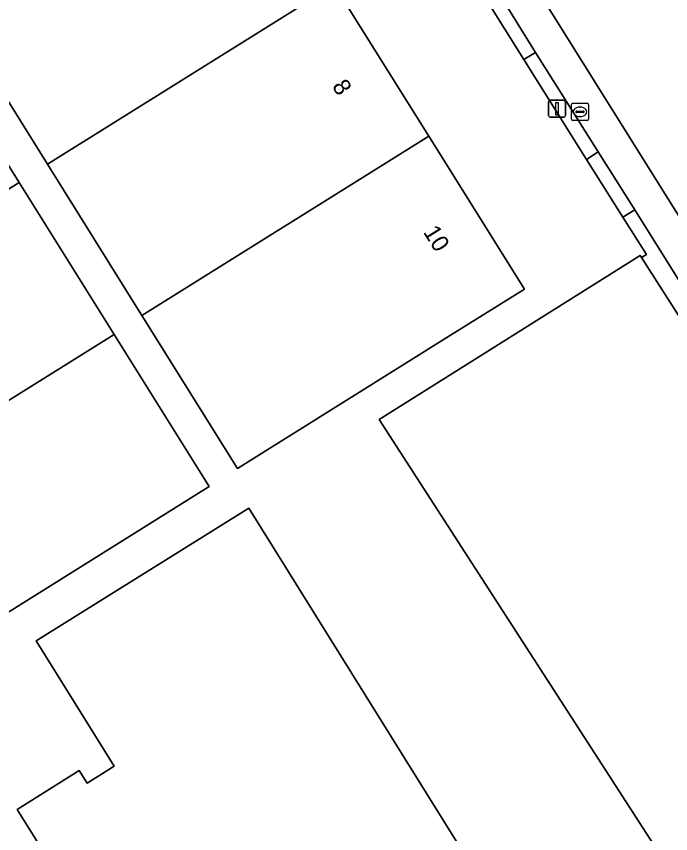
# Model space of a CAD drawing. Extents: x 158455 to 159797, y 387218 to 388672.
# Drawn here: x 158762.56 to 158800.91, y 387815.4 to 387863.3 of the extents above; entities that cross this region are included whole.
import ezdxf

# ---------------------------------------------------------------- set-up
doc = ezdxf.new("R2010")
doc.units = 0
for name, color, linetype in [('IMGEO_Brandkraan', 7, 'Continuous'), ('IMGEO_Erf', 7, 'Continuous'), ('IMGEO_Lichtmast', 7, 'Continuous'), ('IMGEO_Pand', 7, 'Continuous'), ('IMGEO_Pand_nummerreeks', 7, 'Continuous'), ('IMGEO_Parkeervlak_open', 7, 'Continuous'), ('IMGEO_Rijbaan_lokaal_gesloten', 7, 'Continuous'), ('IMGEO_Voetpad_open', 7, 'Continuous')]:
    doc.layers.add(name, color=color, linetype=linetype)

msp = doc.modelspace()

# ---------------------------------------------------------------- linework, layer by layer
at = {"layer": 'IMGEO_Brandkraan'}
for p, q in [((158795.095, 387857.277), (158795.095, 387858.129)), ((158795.17, 387858.203), (158796.022, 387858.203)), ((158795.583, 387857.983), (158795.608, 387857.983)), ((158796.096, 387858.129), (158796.096, 387857.277)), ((158795.354, 387857.697), (158795.354, 387857.709)), ((158795.792, 387857.66), (158795.394, 387857.66)), ((158795.397, 387857.746), (158795.795, 387857.746)), ((158795.606, 387857.423), (158795.581, 387857.423)), ((158795.838, 387857.709), (158795.838, 387857.697)), ((158796.022, 387857.203), (158795.17, 387857.203))]:
    msp.add_line(p, q, dxfattribs=at)
for points in [[(158795.095, 387857.277), (158795.095, 387858.129)], [(158795.17, 387858.203), (158796.022, 387858.203)], [(158796.096, 387858.129), (158796.096, 387857.277)], [(158796.022, 387857.203), (158795.17, 387857.203)]]:
    msp.add_lwpolyline(points, dxfattribs=at)
for centre, radius, start, end in [((158795.172, 387858.127), 0.0765, 91.552, 178.448), ((158795.172, 387858.127), 0.0765, 91.552, 178.448), ((158796.02, 387858.127), 0.0765, 1.552, 88.448), ((158796.02, 387858.127), 0.0765, 1.552, 88.448), ((158795.394, 387857.706), 0.0403, 85.8775, 175.7526), ((158795.391, 387857.696), 0.0366, 178.938, 274.7102), ((158795.795, 387857.703), 0.043, 264.8664, 352.4533), ((158795.799, 387857.708), 0.0386, 1.7309, 96.639), ((158795.172, 387857.279), 0.0765, 181.552, 268.448), ((158795.172, 387857.279), 0.0765, 181.552, 268.448), ((158796.02, 387857.279), 0.0765, 271.552, 358.448), ((158796.02, 387857.279), 0.0765, 271.552, 358.448)]:
    msp.add_arc(centre, radius, start, end, dxfattribs=at)
for centre, major_axis, ratio, start_param, end_param in [((158795.582, 387857.703), (-0.387, 0.002), 0.722429, 4.712389, 7.853982), ((158795.607, 387857.703), (-0.39, 0.002), 0.717154, 1.570796, 4.712389)]:
    msp.add_ellipse(centre, major_axis=major_axis, ratio=ratio, start_param=start_param, end_param=end_param, dxfattribs=at)
at = {"layer": 'IMGEO_Erf'}
for points in [[(158800.488, 387813.876), (158783.815, 387839.674), (158799.126, 387849.283), (158799.192, 387849.165), (158799.495, 387849.349), (158798.107, 387851.535), (158795.971, 387854.919), (158792.311, 387860.769), (158790.068, 387864.352), (158787.01, 387869.188), (158784.775, 387872.783), (158776.797, 387885.577), (158774.665, 387888.991), (158773.366, 387891.042)], [(158771.452, 387802.636), (158762.604, 387816.822), (158766.252, 387819.098), (158766.712, 387818.361), (158768.299, 387819.351), (158763.717, 387826.697), (158776.177, 387834.469), (158789.093, 387813.763)]]:
    msp.add_lwpolyline(points, dxfattribs=at)
for points in [[(158775.523, 387836.811), (158769.92, 387845.776), (158764.379, 387854.641), (158758.776, 387863.607), (158771.346, 387871.463), (158775.586, 387874.113), (158781.189, 387865.148), (158786.73, 387856.283), (158792.333, 387847.317), (158788.093, 387844.667)], [(158761.356, 387827.942), (158757.115, 387825.292), (158751.55, 387834.196), (158745.985, 387843.102), (158740.419, 387852.007), (158744.66, 387854.657), (158757.16, 387862.47), (158762.726, 387853.564), (158768.292, 387844.658), (158773.856, 387835.755)]]:
    msp.add_lwpolyline(points, close=True, dxfattribs=at)
at = {"layer": 'IMGEO_Lichtmast'}
for p, q in [((158793.849, 387858.384), (158794.639, 387858.384)), ((158794.639, 387858.384), (158793.849, 387858.384)), ((158793.749, 387857.484), (158793.749, 387858.284)), ((158793.749, 387858.284), (158793.749, 387857.484)), ((158794.739, 387858.284), (158794.739, 387857.484)), ((158794.739, 387857.484), (158794.739, 387858.284)), ((158794.639, 387857.384), (158793.849, 387857.384)), ((158793.849, 387857.384), (158794.639, 387857.384))]:
    msp.add_line(p, q, dxfattribs=at)
msp.add_lwpolyline([(158794.169, 387858.259), (158794.319, 387858.259), (158794.319, 387857.509), (158794.169, 387857.509), (158794.169, 387858.259)], dxfattribs=at)
for centre, start, end in [((158793.849, 387858.284), 90, 180), ((158793.849, 387858.284), 90, 180), ((158794.639, 387858.284), 0, 90), ((158794.639, 387858.284), 360, 90), ((158793.849, 387857.484), 180, 270), ((158793.849, 387857.484), 180, 270), ((158794.639, 387857.484), 270, 0), ((158794.639, 387857.484), 270, 0)]:
    msp.add_arc(centre, 0.1, start, end, dxfattribs=at)
at = {"layer": 'IMGEO_Pand'}
for points in [[(158764.379, 387854.641), (158781.189, 387865.148), (158775.586, 387874.113), (158771.346, 387871.463), (158758.776, 387863.607)], [(158769.92, 387845.776), (158786.73, 387856.283), (158781.189, 387865.148), (158764.379, 387854.641)], [(158762.726, 387853.564), (158757.16, 387862.47), (158744.66, 387854.657), (158740.419, 387852.007), (158745.985, 387843.102)], [(158769.92, 387845.776), (158775.523, 387836.811), (158788.093, 387844.667), (158792.333, 387847.317), (158786.73, 387856.283)], [(158768.292, 387844.658), (158762.726, 387853.564), (158745.985, 387843.102), (158751.55, 387834.196)], [(158800.488, 387813.876), (158813.131, 387821.784), (158814.073, 387825.912), (158799.192, 387849.165), (158799.126, 387849.283), (158783.815, 387839.674)], [(158768.292, 387844.658), (158751.55, 387834.196), (158757.115, 387825.292), (158761.356, 387827.942), (158773.856, 387835.755)], [(158779.847, 387800.742), (158789.812, 387806.958), (158787.506, 387810.654), (158786.782, 387810.203), (158785.831, 387811.728), (158789.093, 387813.763), (158776.177, 387834.469), (158763.717, 387826.697), (158768.299, 387819.351), (158766.712, 387818.361), (158766.252, 387819.098), (158762.604, 387816.822), (158771.452, 387802.636), (158774.397, 387804.473), (158775.793, 387802.235), (158778.041, 387803.637)]]:
    msp.add_lwpolyline(points, close=True, dxfattribs=at)
at = {"layer": 'IMGEO_Parkeervlak_open'}
for points in [[(158815.162, 387829.602), (158779.898, 387885.947)], [(158779.996, 387884.757), (158779.635, 387882.852), (158779.716, 387882.386), (158785.476, 387873.211), (158787.718, 387869.63), (158790.757, 387864.802), (158792.992, 387861.187), (158796.666, 387855.36), (158798.808, 387851.952), (158811.691, 387831.345), (158811.738, 387831.253), (158812.129, 387830.976), (158813.993, 387830.436)]]:
    msp.add_lwpolyline(points, dxfattribs=at)
at = {"layer": 'IMGEO_Rijbaan_lokaal_gesloten'}
msp.add_lwpolyline([(158809.048, 387852.533), (158782.923, 387894.163), (158777.049, 387890.477), (158779.898, 387885.947), (158815.162, 387829.602)], dxfattribs=at)
at = {"layer": 'IMGEO_Voetpad_open'}
for points in [[(158792.311, 387860.769), (158792.992, 387861.187), (158790.757, 387864.802), (158790.068, 387864.352)], [(158792.311, 387860.769), (158795.971, 387854.919), (158796.666, 387855.36), (158792.992, 387861.187)], [(158798.107, 387851.535), (158798.808, 387851.952), (158796.666, 387855.36), (158795.971, 387854.919)]]:
    msp.add_lwpolyline(points, close=True, dxfattribs=at)
msp.add_lwpolyline([(158811.251, 387831.047), (158811.691, 387831.345), (158798.808, 387851.952), (158798.107, 387851.535), (158799.495, 387849.349), (158799.192, 387849.165), (158814.073, 387825.912), (158813.131, 387821.784), (158800.488, 387813.876), (158800.589, 387813.713), (158798.057, 387812.257), (158799.087, 387810.694), (158808.291, 387816.421), (158807.978, 387816.856)], dxfattribs=at)

# ---------------------------------------------------------------- texts
at = {"layer": 'IMGEO_Pand_nummerreeks'}
for s, p in [('8', (158781.034, 387859.207)), ('10', (158786.373, 387850.665))]:
    msp.add_text(s, height=1, rotation=302.0046, dxfattribs=at).set_placement(p)

doc.saveas('drawing.dxf')
